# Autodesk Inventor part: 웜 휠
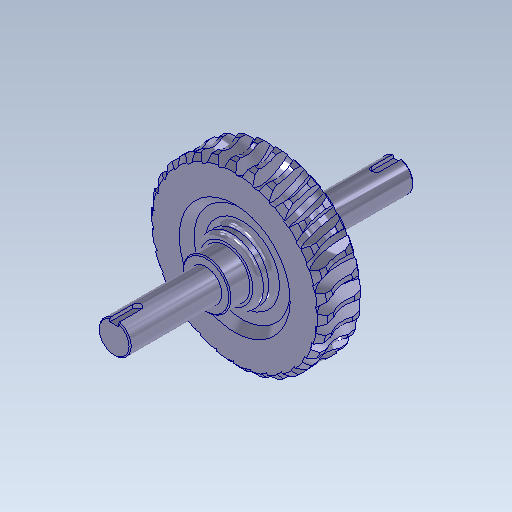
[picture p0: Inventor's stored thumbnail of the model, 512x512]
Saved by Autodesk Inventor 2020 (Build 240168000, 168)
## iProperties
CustomPartVersion: 1
Created: 2013-01
Part Number: 웜 휠
Material: 탄소강
Document SubType Name: Modeling
Designer: 한국산업디자인학원[gmhk.co.kr]
Categories: <?xml version="1.0" encoding="UTF-16"?> <MemberInstance><Categories><FamilyTemplate><FamilyTemplateParameter ValueType="xs:double" Id="1" ObjectReferenceKey="da
Density: 7.87 g/cm^3
Mass: 6989.44 g
Surface Area: 1041.74 cm^2
Volume: 888.112 cm^3
Appearance: _시험-파란색 크롬
Author: 한국산업디자인학원[gmhk.co.kr]
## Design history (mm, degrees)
body "Solid1"
node "톱니 평면"
sketch "기본 본체 스케치"
  geometry: L1 (0, -14)-(0, 14) reference; L2 (0, 20)-(77.639, 20); L3 (77.639, 20)-(82.5, 15.652); L4 (-10, 0)-(60, 0) reference; L5 (82.5, 15.652)-(82.5, -15.652); L6 (0, -20)-(77.639, -20); L7 (0, 20)-(0, -20); L8 (77.639, -20)-(82.5, -15.652); C1 r 20 at (100, 0)
  constraints: 14 end point, 3 symmetric about line, 2 perpendicular, 2 point on line, 1 centre point, 1 collinear
  dimensions: "d50" = 41.8103 deg angle of L3 L2 (= da_fi); "d87" = 165 diameter of L5 L1 (= da_dae); "d89" = 40 diameter of C1 (= 2 x da_aw - da_da); "d92" = 40 distance of L2.start L6.start (= da_b); "d93" = 100 distance from line of C1.centre L7 (= da_aw)
revolve "기본 본체" stored, may be unused: angle "d35" = 90 deg
revolve "기본 본체2" stored, may be unused: angle "d90" = 90 deg
workplane "Work Plane13"
revolve "톱니" stored, may be unused: angle "d43" = 90 deg
pattern_circular "톱니 패턴" dims angle "d46" = 360 deg
workplane "Work Plane14"
workplane "Work Plane15"
revolve "회전6" stored, may be unused: angle "d97" = 90 deg
revolve "회전7" stored, may be unused: angle "d104" = 90 deg
fillet "모깎기1" dims "d105" = 5
chamfer "모따기1" distance "d106" = 1; stored, may be unused: second distance "d107" = 2, angle "d108" = 45 deg
node "작업 평면16"
sketch "스케치11"
  geometry: L1 (-14, 43)-(14, 43) reference; L2 (4, 43)-(4, 22); L3 (-4, 22)-(-4, 43); A1 r 4 centre (0, 22) between (-4, 22) and (4, 22); 2 further points
  constraints: 4 end point, 2 perpendicular, 2 point on circle, 2 point on line, 2 tangent, 1 centre point, 1 midpoint, 1 vertical alignment
  dimensions: "d109" = 8 distance between parallel lines of L2 L3; "d110" = 25 dimension on A1 L1
extrude "돌출1" cut sketch "스케치11" distance "d111" = 4; taper "d112" = 0 deg
mirror "대칭1"
sketch "톱니 스케치"
  geometry: L1 (10, 5.301)-(10, -5.301) reference; L2 (-32.842, 0)-(-12.948, 0) reference; L3 (-90, 6.896)-(-90, -6.896); L4 (-90, -6.896)-(-71, -6.896); L5 (-71, -6.896)-(-59, -2.529); L6 (-59, -2.529)-(-59, 0); L7 (-59, 2.529)-(-71, 6.896); L8 (-71, 6.896)-(-90, 6.896); L9 (-59, 2.529)-(-59, 0); L10 (-65, 0)-(-65, -4.712)
  constraints: 16 end point, 4 perpendicular, 3 equal length, 2 point on line, 1 midpoint, 1 parallel, 1 vertical
  dimensions: "d38" = 100 distance between parallel lines of L1 L3 (= da_aw); "d39" = 20 deg angle of L7 L8 (= da_alfat); "d40" = 19 distance of L7.end L3.start (= 0.5 x da_df1); "d41" = 25 distance between parallel lines of L3 L10 (= 0.5 x da_d1); "d42" = 4.71239 distance of L10.start L10.end (= 0.3 x da_px)
sketch "Sketch8"
  geometry: C1 r 77.639 at (0, 0) reference; C2 r 75 at (0, 0)
  constraints: 1 centre point, 1 coincident
  dimensions: "d77" = 150 diameter of C2 (= da_dw)
body "Srf1"
sketch "스케치9"
  geometry: L1 (-74.283, 20)-(-74.054, 20) reference; L2 (-74.054, 20)-(-74.261, 20) reference; L3 (-74.261, 20)-(-75.727, 20) reference; L4 (-77.355, 20)-(-75.727, 20) reference; L5 (-77.355, 20)-(-77.106, 20) reference; L6 (-77.106, 20)-(-76.222, 20) reference; L7 (-76.222, 20)-(-77.633, 20) reference; L8 (-77.045, 20)-(-77.633, 20) reference; L9 (-77.045, 20)-(-76.789, 20) reference; L10 (-76.789, 20)-(-74.852, 20) reference; L11 (-74.852, 20)-(-76.145, 20) reference; L12 (-73.369, 20)-(-76.145, 20) reference; L13 (-73.369, 20)-(-73.116, 20) reference; L14 (-73.116, 20)-(-70.211, 20) reference; L15 (-70.211, 20)-(-71.33, 20) reference; L16 (-66.486, 20)-(-71.33, 20) reference; L17 (-66.486, 20)-(-66.247, 20) reference; L18 (-66.247, 20)-(-62.501, 20) reference; L19 (-62.501, 20)-(-63.397, 20) reference; L20 (-56.697, 20)-(-63.397, 20) reference; L21 (-56.697, 20)-(-56.483, 20) reference; L22 (-56.483, 20)-(-52.059, 20) reference; L23 (-52.059, 20)-(-52.693, 20) reference; L24 (-44.431, 20)-(-52.693, 20) reference; L25 (-44.431, 20)-(-44.25, 20) reference; L26 (-44.25, 20)-(-39.342, 20) reference; L27 (-39.342, 20)-(-39.687, 20) reference; L28 (-30.222, 20)-(-39.687, 20) reference; L29 (-30.222, 20)-(-30.084, 20) reference; L30 (-30.084, 20)-(-24.906, 20) reference; L31 (-24.906, 20)-(-24.945, 20) reference; L32 (-14.693, 20)-(-24.945, 20) reference; L33 (-14.693, 20)-(-14.602, 20) reference; L34 (-14.602, 20)-(-9.381, 20) reference; L35 (-9.381, 20)-(-9.114, 20) reference; L36 (1.479, 20)-(-9.114, 20) reference; L37 (1.479, 20)-(1.517, 20) reference; L38 (1.517, 20)-(6.554, 20) reference; L39 (6.554, 20)-(7.116, 20) reference; L40 (17.586, 20)-(7.116, 20) reference; L41 (17.586, 20)-(17.571, 20) reference; L42 (17.571, 20)-(22.202, 20) reference; L43 (22.202, 20)-(23.034, 20) reference; L44 (32.924, 20)-(23.034, 20) reference; L45 (32.924, 20)-(32.856, 20) reference; L46 (32.856, 20)-(36.88, 20) reference; L47 (36.88, 20)-(37.946, 20) reference; L48 (46.823, 20)-(37.946, 20) reference; L49 (46.823, 20)-(46.705, 20) reference; L50 (46.705, 20)-(49.946, 20) reference; L51 (49.946, 20)-(51.2, 20) reference; L52 (58.676, 20)-(51.2, 20) reference; L53 (58.676, 20)-(58.514, 20) reference; L54 (58.514, 20)-(60.83, 20) reference; L55 (60.83, 20)-(62.216, 20) reference; L56 (67.965, 20)-(62.216, 20) reference; L57 (67.965, 20)-(67.764, 20) reference; L58 (67.764, 20)-(69.055, 20) reference; L59 (69.055, 20)-(70.512, 20) reference; L60 (74.283, 20)-(70.512, 20) reference; L61 (74.283, 20)-(74.054, 20) reference; L62 (74.054, 20)-(74.261, 20) reference; L63 (74.261, 20)-(75.727, 20) reference; L64 (77.355, 20)-(75.727, 20) reference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
  constraints: 8 end point, 3 point on line, 2 perpendicular, 1 parallel
  dimensions: "d94" = 90 diameter of L122.end L121; "d95" = 135 deg angle of L123 L122; "d96" = 13 distance from line of L121.start L122
node "투영된 루프1"
sketch "스케치10"
  geometry: L1 (45, 13)-(-45, 13) reference; L2 (0, 13)-(0, 133); L3 (0, 133)-(-15, 133); L4 (-15, 133)-(-15, 47); L5 (-15, 47)-(-22.5, 47); L6 (-22.5, 47)-(-22.5, 28); L7 (-22.5, 28)-(-30, 28); L8 (-30, 28)-(-30, 13); L9 (30, 47)-(-30, 47) reference; 1 further point
  constraints: 14 end point, 4 parallel, 3 perpendicular, 1 collinear, 1 midpoint, 1 point on line
  dimensions: "d99" = 30 diameter of L4 L2; "d100" = 45 diameter of L6 L2; "d101" = 60 diameter of L8 L2; "d102" = 15 distance between parallel lines of L7 L1; "d103" = 120 distance of L2.start L2.end
node "참조1"
feature "피치 지름" dims "d78" = 40 (= da_b), "d79" = 0
other parameters: "da_aw" = 100 [user parameter; used in 5 equation terms], "da_fi" = 41.8103 deg [user parameter; used in 1 equation term], "da_b" = 40 [user parameter; used in 2 equation terms], "da_df" = 138 [user parameter], "da_beta" = 1.97396 [user parameter; used in 1 equation term], "da_alfat" = 20 deg [user parameter; used in 1 equation term], "da_df1" = 38 [user parameter; used in 1 equation term], "da_px" = 90 deg [user parameter; used in 1 equation term], "d37" = -1.97396 (computed from da_rightdir, da_beta), "d69" = 0, "d73" = 0, "d75" = 6 deg (computed from da_z), "da_dw" = 150 [user parameter; used in 1 equation term], "da_rightdir" = 0 [user parameter; used in 1 equation term], "d80" = 0, "d81" = 0, "d82" = 0, "d83" = 6 deg (computed from da_z), "d84" = 0, "d85" = 180 deg, "da_dae" = 165 [user parameter; used in 1 equation term]
